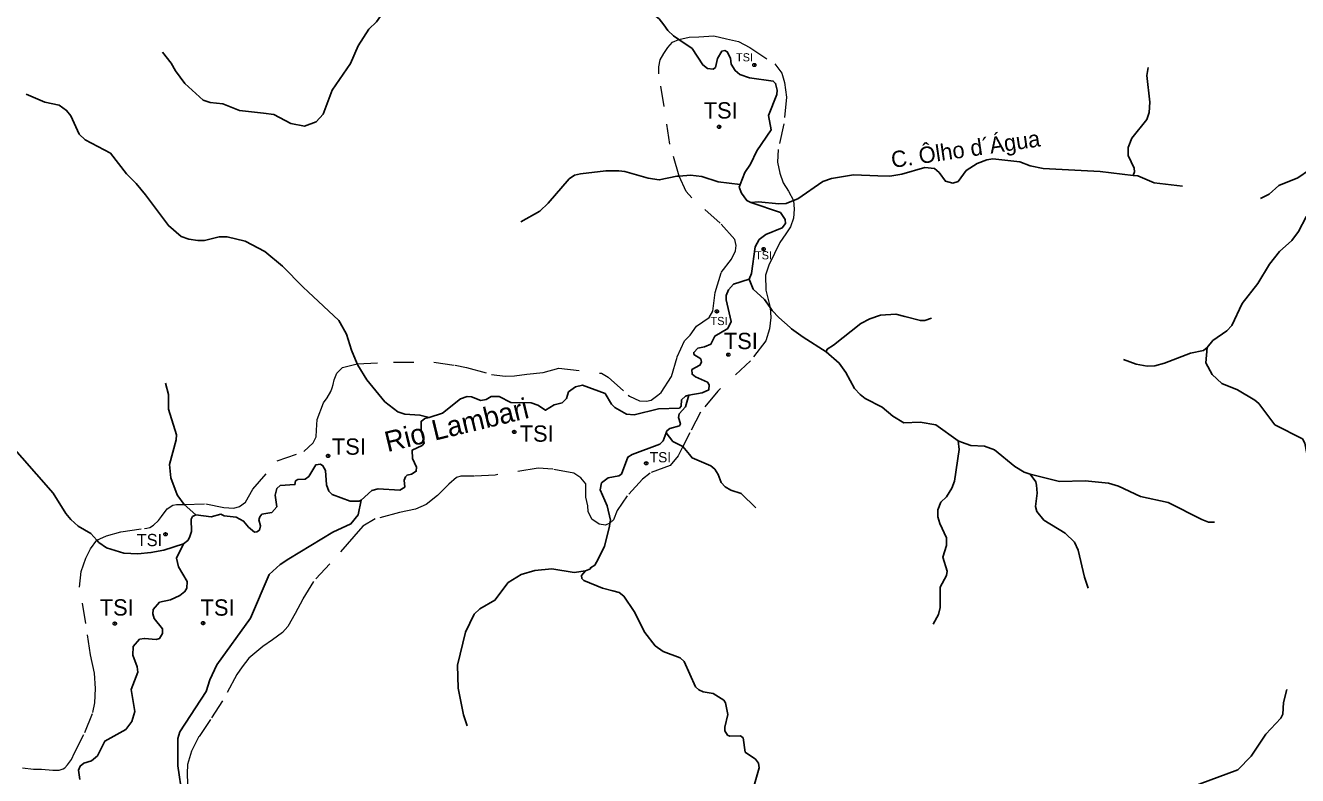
# Model space of a CAD drawing. Extents: x 473.9 to 500, y 7733.1 to 7760.8.
# Drawn here: x 481.48 to 487.72, y 7753.5 to 7757.18 of the extents above; entities that cross this region are included whole.
import ezdxf
from ezdxf.enums import TextEntityAlignment as Align

# ---------------------------------------------------------------- set-up
doc = ezdxf.new("R2010")
doc.units = 0
doc.header["$LTSCALE"] = 0.032
doc.header["$PDMODE"] = 32
doc.header["$PDSIZE"] = 0.016
doc.linetypes.add('SHORT_DASHED', pattern=[2.7, 1.5, -1.2])
doc.layers.add('21', color=7, linetype='SHORT_DASHED', lineweight=13)
doc.layers.add('7', color=7, linetype='Continuous', lineweight=25)
doc.layers.add('61', color=7, linetype='Continuous')

msp = doc.modelspace()

# ---------------------------------------------------------------- linework, layer by layer
at = {"layer": '21'}
for points in [[(484.6887, 7757.1117), (484.7385, 7757.1234), (484.7871, 7757.126), (484.8594, 7757.1302), (484.9218, 7757.1159), (484.9806, 7757.1021), (485.0374, 7757.0728), (485.1595, 7756.9923), (485.1943, 7756.9468), (485.2067, 7756.9021), (485.217, 7756.8289), (485.2033, 7756.6995), (485.1761, 7756.5735), (485.1727, 7756.5105), (485.1846, 7756.4577), (485.1999, 7756.41), (485.2272, 7756.3692), (485.2505, 7756.3229)], [(484.6893, 7756.4425), (484.6449, 7756.599), (484.6159, 7756.7846), (484.5904, 7756.9447), (484.5904, 7756.9787), (484.5972, 7757.0128), (484.6142, 7757.0434), (484.6347, 7757.0723), (484.6568, 7757.0996), (484.6887, 7757.1117)], [(483.1107, 7755.5219), (483.2879, 7755.5298), (483.4871, 7755.5298), (483.5916, 7755.515), (483.6471, 7755.5042), (483.7697, 7755.4702), (483.8361, 7755.4617), (483.8821, 7755.4634), (483.9432, 7755.4708), (484.0237, 7755.4801), (484.1005, 7755.5012), (484.3095, 7755.4757), (484.3422, 7755.4563), (484.44, 7755.369), (484.4462, 7755.3635), (484.4957, 7755.3409), (484.5303, 7755.3382), (484.5535, 7755.3435), (484.5854, 7755.369), (484.6011, 7755.3816), (484.6517, 7755.4596), (484.6805, 7755.5559), (484.7163, 7755.6344), (484.7447, 7755.662), (484.7747, 7755.7062), (484.838, 7755.7486), (484.8555, 7755.781), (484.8666, 7755.8725), (484.896, 7755.9696), (484.9468, 7756.0356), (484.9672, 7756.0756), (484.9701, 7756.1023), (484.9627, 7756.1314), (484.8913, 7756.2121), (484.7514, 7756.3366), (484.7249, 7756.3675), (484.6893, 7756.4425)], [(485.2505, 7756.3229), (485.2544, 7756.2806), (485.251, 7756.2364), (485.2357, 7756.1938), (485.2136, 7756.1597), (485.1846, 7756.1172), (485.1574, 7756.0627), (485.1301, 7756.0065), (485.1131, 7755.9571), (485.1148, 7755.8839), (485.1363, 7755.7983)], [(485.1363, 7755.7983), (485.1403, 7755.7494), (485.1335, 7755.6932), (485.115, 7755.6355), (485.0399, 7755.5366), (484.8798, 7755.3885), (484.7947, 7755.2846), (484.7419, 7755.1841), (484.7084, 7755.1169)], [(482.2619, 7754.8324), (482.3685, 7754.8351), (482.457, 7754.8181), (482.5047, 7754.8147), (482.5336, 7754.8232), (482.5626, 7754.8436), (482.5983, 7754.9071), (482.7174, 7755.0464), (482.8496, 7755.0915), (482.8948, 7755.135), (482.9089, 7755.164), (482.911, 7755.196), (482.915, 7755.2488), (482.9452, 7755.3309), (482.9641, 7755.3554), (482.9811, 7755.386), (482.9881, 7755.4048), (482.9925, 7755.4214), (482.9969, 7755.4437), (483.0104, 7755.477), (483.0393, 7755.5042), (483.1107, 7755.5219)], [(484.7084, 7755.1169), (484.6857, 7755.0701), (484.6466, 7755.0239), (484.5476, 7754.9864), (484.5104, 7754.9562), (484.4355, 7754.8743), (484.3861, 7754.8028), (484.3673, 7754.7568), (484.3504, 7754.7404)], [(484.3504, 7754.7404), (484.3282, 7754.7312), (484.2975, 7754.7364), (484.2618, 7754.7602), (484.2431, 7754.7976), (484.2414, 7754.8249), (484.2329, 7754.8675), (484.2319, 7754.9343), (484.208, 7754.9624), (484.1734, 7754.9851), (484.0699, 7755.0052), (483.9976, 7755.0109), (483.787, 7754.9764), (483.685, 7754.9706), (483.6191, 7754.9714), (483.5978, 7754.9645), (483.5603, 7754.9322), (483.5041, 7754.876), (483.4496, 7754.8317), (483.3969, 7754.8096), (483.3185, 7754.7925), (483.1994, 7754.7619), (483.1381, 7754.7261), (483.0938, 7754.6751), (482.9763, 7754.5406), (482.8963, 7754.4554), (482.8435, 7754.3686), (482.806, 7754.2971), (482.7703, 7754.2341), (482.7448, 7754.2051), (482.6954, 7754.1694), (482.6477, 7754.1353), (482.5796, 7754.0791), (482.5455, 7754.0366), (482.52, 7753.9991), (482.4502, 7753.8697), (482.3906, 7753.7778), (482.3344, 7753.6943), (482.297, 7753.6228), (482.2782, 7753.5581), (482.2765, 7753.5139), (482.2782, 7753.4628)], [(481.8339, 7754.6566), (481.8815, 7754.6785), (481.9513, 7754.6989), (482.0676, 7754.7149), (482.0789, 7754.7162), (482.0929, 7754.7197), (482.1113, 7754.7311), (482.1353, 7754.7534), (482.1501, 7754.7726), (482.1786, 7754.811), (482.2067, 7754.8283), (482.2237, 7754.8317), (482.2619, 7754.8324)], [(481.4679, 7753.5409), (481.4695, 7753.541), (481.5223, 7753.5349), (481.5625, 7753.534), (481.6176, 7753.53), (481.6486, 7753.53), (481.6591, 7753.5322), (481.6678, 7753.5357), (481.6765, 7753.5418), (481.6888, 7753.5558), (481.7093, 7753.5816), (481.7246, 7753.6148), (481.7743, 7753.7148), (481.8134, 7753.8118), (481.8236, 7753.8595), (481.827, 7753.9293), (481.8219, 7754.0059), (481.8015, 7754.0945), (481.7794, 7754.2494), (481.7487, 7754.4265), (481.7572, 7754.5031), (481.7794, 7754.5695), (481.8015, 7754.6155), (481.8339, 7754.6566)]]:
    msp.add_lwpolyline(points, dxfattribs=at)
for p in [(485.0589, 7756.9873), (484.8857, 7756.6841), (485.1044, 7756.0844), (484.8749, 7755.7791), (484.9311, 7755.5669), (483.881, 7755.188), (482.9679, 7755.0705), (484.5284, 7755.0343), (482.1704, 7754.6862), (482.3546, 7754.2505), (481.9216, 7754.2483)]:
    msp.add_point(p, dxfattribs=at)
at = {"layer": '7'}
msp.add_line((482.2619, 7754.8324), (482.3191, 7754.7821), dxfattribs=at)
for points in [[(484.3617, 7757.6785), (484.3696, 7757.6537), (484.3997, 7757.6046), (484.4076, 7757.5725), (484.4085, 7757.5496), (484.3995, 7757.5253), (484.3562, 7757.4607), (484.3525, 7757.4238), (484.3665, 7757.3869), (484.3918, 7757.3498), (484.4257, 7757.3168), (484.4991, 7757.267), (484.5622, 7757.2371), (484.5917, 7757.2129), (484.6147, 7757.1838), (484.6338, 7757.1564), (484.6615, 7757.1301), (484.6887, 7757.1117)], [(482.1549, 7757.0494), (482.1985, 7756.996), (482.2187, 7756.9591), (482.2656, 7756.8963), (482.3553, 7756.8147), (482.389, 7756.8041), (482.4519, 7756.7976), (482.5337, 7756.764), (482.6514, 7756.7505), (482.7024, 7756.7446), (482.7852, 7756.7008), (482.8516, 7756.6878), (482.9087, 7756.7087), (482.9433, 7756.7465), (482.9877, 7756.8632), (483.0778, 7756.9951), (483.1148, 7757.0805), (483.1682, 7757.1627), (483.2053, 7757.1995), (483.2529, 7757.2663)], [(484.6887, 7757.1117), (484.7535, 7757.0677), (484.8062, 7756.9875), (484.8293, 7756.9698), (484.8565, 7756.9666), (484.8683, 7756.9751), (484.8787, 7757.0189), (484.8993, 7757.0545), (484.9143, 7757.0579), (484.9261, 7757.0523), (484.9412, 7757.0206), (484.9456, 7756.991), (484.9643, 7756.96), (484.9884, 7756.9414), (485.0344, 7756.9246), (485.1514, 7756.9083), (485.1632, 7756.8966), (485.1712, 7756.8639), (485.1688, 7756.8434), (485.1278, 7756.7397), (485.1418, 7756.6696), (485.0704, 7756.5667), (485.0408, 7756.5003), (485.0124, 7756.4609), (484.9888, 7756.4012)], [(486.9901, 7756.9758), (486.9847, 7756.9366), (486.9983, 7756.8043), (486.9952, 7756.7547), (486.9835, 7756.72), (486.9111, 7756.6279), (486.8925, 7756.5824), (486.8925, 7756.5437), (486.9229, 7756.4815), (486.9245, 7756.4636), (486.9174, 7756.4449)], [(481.4867, 7756.8443), (481.5789, 7756.8057), (481.6494, 7756.7903), (481.6853, 7756.7642), (481.7057, 7756.7382), (481.7468, 7756.6477), (481.7758, 7756.62), (481.8998, 7756.5546), (481.9793, 7756.4538), (482.0266, 7756.4069), (482.0723, 7756.35), (482.1846, 7756.1995), (482.2472, 7756.1469), (482.2854, 7756.1325), (482.3282, 7756.1273), (482.3615, 7756.1274), (482.4334, 7756.144), (482.4733, 7756.1441), (482.5618, 7756.1238), (482.6578, 7756.0733), (482.7445, 7756.0002), (482.8458, 7755.8973), (482.8702, 7755.8746), (483.0207, 7755.7345), (483.0273, 7755.7229), (483.0586, 7755.668), (483.0823, 7755.5888), (483.1107, 7755.5219)], [(487.5421, 7756.3323), (487.5839, 7756.3541), (487.6324, 7756.397), (487.725, 7756.4345), (487.7822, 7756.4727), (487.8302, 7756.5142), (487.8783, 7756.5705)], [(486.9174, 7756.4449), (486.7549, 7756.4656), (486.4755, 7756.48), (486.4119, 7756.4934), (486.3609, 7756.5129), (486.228, 7756.5265), (486.2, 7756.5226), (486.1514, 7756.5048), (486.0985, 7756.4702), (486.058, 7756.4162), (486.0333, 7756.408), (485.9965, 7756.4174), (485.9662, 7756.4595), (485.9422, 7756.48), (485.8957, 7756.4841), (485.7817, 7756.4518), (485.7232, 7756.4416), (485.6641, 7756.444), (485.5456, 7756.4489), (485.4367, 7756.4312), (485.3956, 7756.4156), (485.2723, 7756.3314), (485.2505, 7756.3229)], [(483.9139, 7756.2183), (484.0062, 7756.271), (484.0469, 7756.3094), (484.1511, 7756.4294), (484.1761, 7756.4472), (484.2065, 7756.4544), (484.3304, 7756.4681), (484.3948, 7756.468), (484.4241, 7756.4646), (484.5381, 7756.432), (484.5921, 7756.4239), (484.6783, 7756.4417), (484.6893, 7756.4425)], [(484.6893, 7756.4425), (484.7457, 7756.4464), (484.8011, 7756.4409), (484.882, 7756.4151), (484.9888, 7756.4012)], [(487.1586, 7756.3925), (487.0206, 7756.4096), (486.9406, 7756.4432), (486.9174, 7756.4449)], [(484.9888, 7756.4012), (484.9852, 7756.3877), (484.9959, 7756.3582), (485.0216, 7756.3229), (485.0418, 7756.3137)], [(485.2505, 7756.3229), (485.2144, 7756.3088), (485.1788, 7756.3062), (485.0792, 7756.3165), (485.0418, 7756.3137)], [(485.0418, 7756.3137), (485.1866, 7756.2648), (485.2096, 7756.2305), (485.2123, 7756.2096), (485.1958, 7756.1893), (485.1146, 7756.1569), (485.0833, 7756.1312), (485.0626, 7756.096), (485.0442, 7755.9657), (485.0337, 7755.9369)], [(487.2806, 7755.6013), (487.308, 7755.6357), (487.3764, 7755.6837), (487.401, 7755.7106), (487.4524, 7755.8173), (487.5289, 7755.9153), (487.5856, 7756.0111), (487.6355, 7756.0725), (487.6956, 7756.1271), (487.7287, 7756.1707), (487.7652, 7756.2421), (487.818, 7756.3076)], [(485.0337, 7755.9369), (484.9569, 7755.9123), (484.9326, 7755.8854), (484.9214, 7755.8575), (484.9209, 7755.8365), (484.9459, 7755.7298), (484.9287, 7755.6952), (484.8654, 7755.6578), (484.8462, 7755.618), (484.8149, 7755.6051), (484.7818, 7755.5996), (484.7619, 7755.5783), (484.7628, 7755.568), (484.7971, 7755.546), (484.7996, 7755.5309), (484.7916, 7755.5148), (484.7525, 7755.4937), (484.7537, 7755.4711), (484.7694, 7755.4581), (484.8285, 7755.4323), (484.8379, 7755.4193), (484.8364, 7755.3947), (484.8026, 7755.3792), (484.7375, 7755.3691)], [(485.1363, 7755.7983), (485.1091, 7755.8373), (485.0537, 7755.8881), (485.0337, 7755.9369)], [(485.412, 7755.5815), (485.2983, 7755.652), (485.2411, 7755.6933), (485.2344, 7755.6994), (485.1797, 7755.749), (485.1463, 7755.7839), (485.1363, 7755.7983)], [(485.9273, 7755.7456), (485.8952, 7755.734), (485.8733, 7755.7337), (485.7978, 7755.7534), (485.7536, 7755.7649), (485.677, 7755.76), (485.6249, 7755.7429), (485.5812, 7755.72), (485.4474, 7755.613), (485.4155, 7755.5939), (485.412, 7755.5815)], [(486.0591, 7755.1447), (485.9496, 7755.2228), (485.8723, 7755.2357), (485.7919, 7755.2334), (485.7379, 7755.2646), (485.6852, 7755.3098), (485.6029, 7755.3528), (485.5773, 7755.3723), (485.5504, 7755.4012), (485.5082, 7755.4788), (485.4751, 7755.5257), (485.412, 7755.5815)], [(486.8703, 7755.544), (486.9321, 7755.5209), (486.9859, 7755.5111), (487.023, 7755.5124), (487.0715, 7755.5247), (487.1986, 7755.5745), (487.2619, 7755.5873), (487.2806, 7755.6013)], [(487.809, 7754.9939), (487.7694, 7755.083), (487.7589, 7755.1332), (487.7472, 7755.1538), (487.6124, 7755.2226), (487.5339, 7755.3268), (487.5145, 7755.3444), (487.4295, 7755.3946), (487.3523, 7755.4254), (487.3051, 7755.4693), (487.2734, 7755.5272), (487.2806, 7755.6013)], [(483.1107, 7755.5219), (483.1136, 7755.515), (483.1571, 7755.4442), (483.2466, 7755.3349), (483.3106, 7755.2862), (483.3449, 7755.276), (483.4186, 7755.2708), (483.4642, 7755.2593)], [(482.1704, 7755.4277), (482.1844, 7755.372), (482.1846, 7755.2992), (482.2245, 7755.1734), (482.2229, 7755.1491), (482.1893, 7755.0279), (482.1957, 7754.9622), (482.2271, 7754.8795), (482.23, 7754.8755), (482.2619, 7754.8324)], [(484.7375, 7755.3691), (484.7212, 7755.3633), (484.7023, 7755.3453), (484.6994, 7755.3141), (484.6914, 7755.3038), (484.5889, 7755.3008), (484.469, 7755.2716), (484.4312, 7755.2756), (484.3739, 7755.3075), (484.3576, 7755.3238), (484.3268, 7755.3763), (484.2159, 7755.4173), (484.1822, 7755.4091), (484.1467, 7755.3842), (484.1369, 7755.3522), (484.1156, 7755.3308), (484.0768, 7755.3213), (484.0346, 7755.2948), (483.997, 7755.3201), (483.9647, 7755.3306), (483.8648, 7755.3317), (483.8064, 7755.362), (483.7686, 7755.361), (483.7426, 7755.3467), (483.7167, 7755.3416), (483.6713, 7755.36), (483.6493, 7755.3618), (483.6174, 7755.3509), (483.5291, 7755.2801), (483.4642, 7755.2593)], [(481.2873, 7755.3318), (481.3035, 7755.284), (481.3429, 7755.2123), (481.3853, 7755.1545), (481.6194, 7754.8875), (481.6812, 7754.7882), (481.7064, 7754.7588), (481.7416, 7754.726), (481.8047, 7754.6895), (481.8339, 7754.6566)], [(484.6262, 7755.1831), (484.6288, 7755.1927), (484.6446, 7755.2056), (484.6915, 7755.2186), (484.6961, 7755.2271), (484.686, 7755.2584), (484.6908, 7755.2761), (484.7214, 7755.3116), (484.7375, 7755.3691)], [(483.4642, 7755.2593), (483.4425, 7755.2541), (483.4239, 7755.2395), (483.4238, 7755.1966), (483.4392, 7755.1332), (483.429, 7755.1212), (483.3799, 7755.098), (483.3817, 7755.0573), (483.4021, 7755.0161), (483.4, 7754.9956), (483.3775, 7754.9811), (483.3554, 7754.9764), (483.3473, 7754.9677), (483.3417, 7754.9523), (483.3441, 7754.9173), (483.3205, 7754.9019), (483.2137, 7754.9091), (483.1826, 7754.9016), (483.1296, 7754.8539)], [(484.3504, 7754.7404), (484.3524, 7754.7562), (484.337, 7754.8261), (484.3022, 7754.9039), (484.3086, 7754.9378), (484.3417, 7754.9622), (484.3943, 7754.9725), (484.4074, 7754.9814), (484.4384, 7755.0644), (484.459, 7755.077), (484.5951, 7755.128), (484.6115, 7755.1439), (484.6262, 7755.1831)], [(484.7084, 7755.1169), (484.6593, 7755.1415), (484.6262, 7755.1831)], [(485.9353, 7754.2458), (485.9615, 7754.2925), (485.9712, 7754.3265), (485.971, 7754.4264), (486.0019, 7754.4843), (486.0049, 7754.5054), (485.9833, 7754.5735), (486.0016, 7754.6305), (486.0017, 7754.6696), (485.9687, 7754.7389), (485.9594, 7754.7716), (485.9585, 7754.8063), (485.9735, 7754.8434), (486.0009, 7754.8693), (486.0284, 7754.9125), (486.0404, 7754.9461), (486.0634, 7755.1026), (486.0591, 7755.1447)], [(486.4122, 7754.9813), (486.3817, 7754.991), (486.3363, 7755.0182), (486.2363, 7755.0996), (486.1882, 7755.1179), (486.1215, 7755.121), (486.0752, 7755.1378), (486.0591, 7755.1447)], [(485.0659, 7754.8163), (484.9946, 7754.8861), (484.9435, 7754.9024), (484.9151, 7754.9185), (484.8967, 7754.9409), (484.8819, 7754.9801), (484.8648, 7755.0048), (484.8456, 7755.0214), (484.7536, 7755.0616), (484.7411, 7755.0768), (484.7084, 7755.1169)], [(483.1296, 7754.8539), (483.1205, 7754.8485), (483.0759, 7754.8479), (482.9874, 7754.8818), (482.9715, 7754.8973), (482.9593, 7754.9289), (482.9556, 7754.9996), (482.9427, 7755.0224), (482.931, 7755.0301), (482.9084, 7755.027), (482.874, 7754.9698), (482.8554, 7754.9572), (482.8192, 7754.9548), (482.8076, 7754.9477), (482.8051, 7754.9303), (482.7333, 7754.9246), (482.7157, 7754.9107), (482.7087, 7754.8778), (482.7165, 7754.8216), (482.6918, 7754.7928), (482.643, 7754.7843), (482.6328, 7754.7724), (482.6286, 7754.7567), (482.636, 7754.7275), (482.6309, 7754.7068), (482.6189, 7754.6983), (482.6066, 7754.697), (482.5769, 7754.7213), (482.553, 7754.7512), (482.5176, 7754.7699), (482.4574, 7754.7771), (482.4417, 7754.785), (482.3941, 7754.7724), (482.3191, 7754.7821)], [(487.3159, 7754.7454), (487.2871, 7754.7464), (487.2547, 7754.758), (487.0884, 7754.8427), (486.954, 7754.8716), (486.8447, 7754.9221), (486.7959, 7754.9367), (486.682, 7754.9479), (486.5551, 7754.9455), (486.4122, 7754.9813)], [(486.6958, 7754.4212), (486.6778, 7754.4763), (486.6481, 7754.6081), (486.6291, 7754.6482), (486.5844, 7754.6923), (486.4782, 7754.7561), (486.4453, 7754.7977), (486.4387, 7754.8226), (486.4467, 7754.8871), (486.4435, 7754.9278), (486.4394, 7754.9438), (486.4122, 7754.9813)], [(483.1296, 7754.8539), (483.1149, 7754.7823), (483.0796, 7754.7372), (482.9905, 7754.6958), (482.7757, 7754.5657), (482.7324, 7754.5381), (482.6795, 7754.4882), (482.5869, 7754.2753), (482.4227, 7754.0463), (482.3873, 7753.9719), (482.369, 7753.9149), (482.2405, 7753.7174), (482.2311, 7753.6852), (482.2306, 7753.551), (482.2522, 7753.407)], [(482.3191, 7754.7821), (482.3032, 7754.773), (482.2956, 7754.7608), (482.2977, 7754.6994), (482.2886, 7754.6705), (482.2793, 7754.6552), (482.2582, 7754.6388)], [(484.2308, 7754.5072), (484.2551, 7754.5171), (484.2551, 7754.5222), (484.2756, 7754.5353), (484.2933, 7754.5641), (484.3234, 7754.6276), (484.3485, 7754.7245), (484.3504, 7754.7404)], [(482.2582, 7754.6388), (482.2234, 7754.5695), (482.2335, 7754.5274), (482.2762, 7754.4544), (482.2756, 7754.4224), (482.2655, 7754.4053), (482.2413, 7754.3867), (482.1945, 7754.3644), (482.1412, 7754.3528), (482.1092, 7754.3167), (482.1073, 7754.2968), (482.1148, 7754.2735), (482.1555, 7754.2219), (482.1563, 7754.1989), (482.1408, 7754.1744), (482.1252, 7754.17), (482.0667, 7754.176), (482.0431, 7754.1712), (482.0118, 7754.1367), (482.0095, 7754.0939), (482.0315, 7754.036), (482.0348, 7754.0108), (482.0024, 7753.9244), (482.0192, 7753.8171), (482.0054, 7753.7681), (481.9754, 7753.7294), (481.8734, 7753.6718), (481.8362, 7753.6002), (481.8071, 7753.5754), (481.7692, 7753.5632), (481.7519, 7753.5497), (481.7437, 7753.5302), (481.7497, 7753.4837)], [(481.8339, 7754.6566), (481.843, 7754.6463), (481.88, 7754.6199), (481.9664, 7754.5937), (482.035, 7754.591), (482.0987, 7754.5967), (482.1619, 7754.6077), (482.2582, 7754.6388)], [(483.6507, 7753.7469), (483.6329, 7753.8016), (483.6053, 7753.9317), (483.602, 7754.0449), (483.6418, 7754.2056), (483.6851, 7754.2942), (483.7128, 7754.3214), (483.7862, 7754.3624), (483.8519, 7754.4496), (483.9144, 7754.4883), (483.9817, 7754.5093), (484.0648, 7754.5173), (484.1753, 7754.4981), (484.2308, 7754.5072)], [(485.0603, 7753.4604), (485.0828, 7753.5407), (485.0788, 7753.5632), (485.0652, 7753.5832), (485.0144, 7753.6184), (485.0045, 7753.6877), (484.9909, 7753.6987), (484.9393, 7753.6966), (484.9273, 7753.7013), (484.9146, 7753.7219), (484.9134, 7753.7407), (484.9288, 7753.8028), (484.918, 7753.8592), (484.9089, 7753.8725), (484.8569, 7753.905), (484.8075, 7753.9144), (484.7867, 7753.9231), (484.7709, 7753.9378), (484.7138, 7754.0622), (484.6955, 7754.0803), (484.6123, 7754.1116), (484.5721, 7754.1397), (484.522, 7754.2052), (484.4697, 7754.307), (484.4188, 7754.3821), (484.3952, 7754.4008), (484.3651, 7754.4089), (484.3146, 7754.4225), (484.2232, 7754.4603), (484.2131, 7754.4699), (484.211, 7754.4841), (484.2308, 7754.5072)], [(487.671, 7753.9257), (487.6551, 7753.8617), (487.6509, 7753.8037), (487.642, 7753.7843), (487.5676, 7753.7056), (487.4959, 7753.599), (487.4299, 7753.5316), (487.2405, 7753.4613), (487.0722, 7753.386), (486.9996, 7753.3382), (486.9192, 7753.2853), (486.8205, 7753.1711), (486.7836, 7753.1389), (486.7449, 7753.1182), (486.6061, 7753.0928)]]:
    msp.add_lwpolyline(points, dxfattribs=at)

# ---------------------------------------------------------------- texts
at = {"layer": '61'}
for height, p in [(0.04, (485.0105, 7757.005)), (0.08, (484.8938, 7756.7248)), (0.04, (485.1038, 7756.0342)), (0.04, (484.8857, 7755.712)), (0.08, (484.9929, 7755.5941)), (0.08, (483.9912, 7755.14)), (0.08, (483.07, 7755.0762)), (0.05, (484.5983, 7755.0389)), (0.06, (482.0913, 7754.628)), (0.08, (481.931, 7754.2876)), (0.08, (482.4258, 7754.2871))]:
    msp.add_text('TSI', height=height, dxfattribs=at).set_placement(p, align=Align.CENTER)
for s, height, rotation, p in [('C. Ôlho d´Água ', 0.08, 8.314, (486.1154, 7756.5377)), ('Rio Lambari', 0.1, 13.594, (483.6096, 7755.1736))]:
    msp.add_text(s, height=height, rotation=rotation, dxfattribs=at).set_placement(p, align=Align.CENTER)

doc.saveas('drawing.dxf')
